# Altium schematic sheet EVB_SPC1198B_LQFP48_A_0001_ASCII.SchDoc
size A4; 项目编号: SPSZ2023-052501A; 项目名称: 三相PFC-2.2KW压机+700W风机
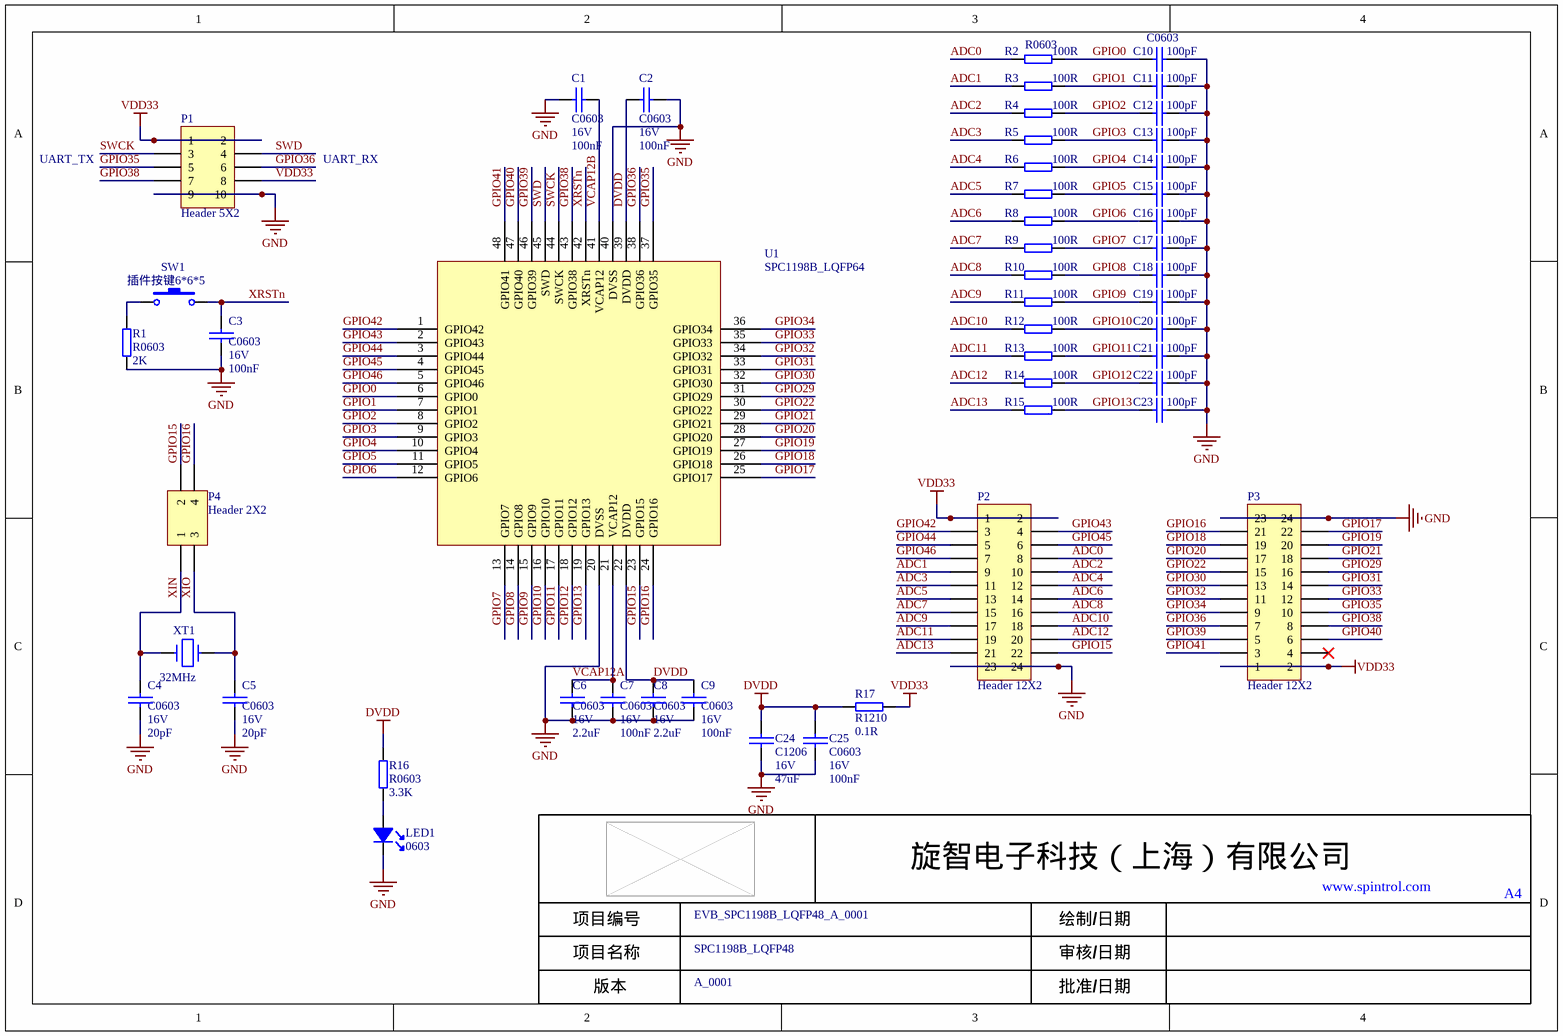
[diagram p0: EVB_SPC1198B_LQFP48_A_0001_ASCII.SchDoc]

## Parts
C1  4.物料简述: C0603  3.物料描述（系统）: 16V  [0603C]  (hidden comment: 100nF)
C2  4.物料简述: C0603  3.物料描述（系统）: 16V  [0603C]  (hidden comment: 100nF)
C3  4.物料简述: C0603  3.物料描述（系统）: 16V  [0603C]  (hidden comment: 100nF)
C4  4.物料简述: C0603  3.物料描述（系统）: 16V  [0603C]  (hidden comment: 20pF)
C5  4.物料简述: C0603  3.物料描述（系统）: 16V  [0603C]  (hidden comment: 20pF)
C6  4.物料简述: C0603  3.物料描述（系统）: 16V  [0603C]  (hidden comment: 2.2uF)
C7  4.物料简述: C0603  3.物料描述（系统）: 16V  [0603C]  (hidden comment: 100nF)
C8  4.物料简述: C0603  3.物料描述（系统）: 16V  [0603C]  (hidden comment: 2.2uF)
C9  4.物料简述: C0603  3.物料描述（系统）: 16V  [0603C]  (hidden comment: 100nF)
C10  4.物料简述: C0603  [0603C]  (hidden comment: 100pF)
C11  100pF  [0603C]
C12  100pF  [0603C]
C13  100pF  [0603C]
C14  100pF  [0603C]
C15  100pF  [0603C]
C16  100pF  [0603C]
C17  100pF  [0603C]
C18  100pF  [0603C]
C19  100pF  [0603C]
C20  100pF  [0603C]
C21  100pF  [0603C]
C22  100pF  [0603C]
C23  100pF  [0603C]
C24  4.物料简述: C1206  3.物料描述（系统）: 16V  [1206C]  (hidden comment: 47uF)
C25  4.物料简述: C0603  3.物料描述（系统）: 16V  [0603C]  (hidden comment: 100nF)
LED1  4.物料简述: 0603  [LED0603]
P1  Header 5X2  [HDR2X5]
P2  Header 12X2  [HDR2X12]
P3  Header 12X2  [HDR2X12]
P4  Header 2X2  [HDR2X2]
R1  4.物料简述: R0603  [0603R]  (hidden comment: 2K)
R2  4.物料简述: R0603  [0603R]  (hidden comment: 100R)
R3  100R  [0603R]
R4  100R  [0603R]
R5  100R  [0603R]
R6  100R  [0603R]
R7  100R  [0603R]
R8  100R  [0603R]
R9  100R  [0603R]
R10  100R  [0603R]
R11  100R  [0603R]
R12  100R  [0603R]
R13  100R  [0603R]
R14  100R  [0603R]
R15  100R  [0603R]
R16  4.物料简述: R0603  [0603R]  (hidden comment: 3.3K)
R17  4.物料简述: R1210  [1210R]  (hidden comment: 0.1R)
SW1  插件按键6*6*5  [Key_6*6]
U1  SPC1198B_LQFP64  [LQFP-48-0.5]
XT1  32MHz  [XT-HI]

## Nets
DVDD: C2.2 C8.2 C9.2 C24.2 C25.2 R16.1 R17.1 U1.22(DVDD) U1.39(DVDD)
GND: C1.2 C2.1 C3.1 C4.1 C5.1 C6.1 C7.1 C8.1 C9.1 C10.2 C11.2 C12.2 C13.2 C14.2 C15.2 C16.2 C17.2 C18.2 C19.2 C20.2 C21.2 C22.2 C23.2 C24.1 C25.1 LED1.K P1.9 P1.10 P2.23 P2.24 P3.23 P3.24 R1.2 U1.20(DVSS) U1.40(DVSS)
VDD33: P1.1 P1.2 P1.8 P2.1 P2.2 P3.1 P3.2 R17.2
ADC0: P2.8 R2.2
ADC1: P2.9 R3.2
ADC2: P2.10 R4.2
ADC3: P2.11 R5.2
ADC4: P2.12 R6.2
ADC5: P2.13 R7.2
ADC6: P2.14 R8.2
ADC7: P2.15 R9.2
ADC8: P2.16 R10.2
ADC9: P2.17 R11.2
ADC10: P2.18 R12.2
ADC11: P2.19 R13.2
ADC12: P2.20 R14.2
ADC13: P2.21 R15.2
GPIO0: C10.1 R2.1 U1.6(GPIO0)
GPIO1: C11.1 R3.1 U1.7(GPIO1)
GPIO2: C12.1 R4.1 U1.8(GPIO2)
GPIO3: C13.1 R5.1 U1.9(GPIO3)
GPIO4: C14.1 R6.1 U1.10(GPIO4)
GPIO5: C15.1 R7.1 U1.11(GPIO5)
GPIO6: C16.1 R8.1 U1.12(GPIO6)
GPIO7: C17.1 R9.1 U1.13(GPIO7)
GPIO8: C18.1 R10.1 U1.14(GPIO8)
GPIO9: C19.1 R11.1 U1.15(GPIO9)
GPIO10: C20.1 R12.1 U1.16(GPIO10)
GPIO11: C21.1 R13.1 U1.17(GPIO11)
GPIO12: C22.1 R14.1 U1.18(GPIO12)
GPIO13: C23.1 R15.1 U1.19(GPIO13)
GPIO15: P2.22 P4.2 U1.23(GPIO15)
GPIO16: P3.21 P4.4 U1.24(GPIO16)
GPIO17: P3.22 U1.25(GPIO17)
GPIO18: P3.19 U1.26(GPIO18)
GPIO19: P3.20 U1.27(GPIO19)
GPIO20: P3.17 U1.28(GPIO20)
GPIO21: P3.18 U1.29(GPIO21)
GPIO22: P3.15 U1.30(GPIO22)
GPIO29: P3.16 U1.31(GPIO29)
GPIO30: P3.13 U1.32(GPIO30)
GPIO31: P3.14 U1.33(GPIO31)
GPIO32: P3.11 U1.34(GPIO32)
GPIO33: P3.12 U1.35(GPIO33)
GPIO34: P3.9 U1.36(GPIO34)
GPIO35: P1.5 P3.10 U1.37(GPIO35)
GPIO36: P1.6 P3.7 U1.38(GPIO36)
GPIO38: P1.7 P3.8 U1.43(GPIO38)
GPIO39: P3.5 U1.46(GPIO39)
GPIO40: P3.6 U1.47(GPIO40)
GPIO41: P3.3 U1.48(GPIO41)
GPIO42: P2.3 U1.1(GPIO42)
GPIO43: P2.4 U1.2(GPIO43)
GPIO44: P2.5 U1.3(GPIO44)
GPIO45: P2.6 U1.4(GPIO45)
GPIO46: P2.7 U1.5(GPIO46)
SWCK: P1.3 U1.44(SWCK)
SWD: P1.4 U1.45(SWD)
VCAP12A: C6.2 C7.2 U1.21(VCAP12)
VCAP12B: C1.1 U1.41(VCAP12)
XIN: C4.2 P4.1 XT1.1
XIO: C5.2 P4.3 XT1.2
XRSTn: C3.2 SW1.1 U1.42(XRSTn)
NetLED1_A: LED1.A R16.2
NetR1_1: R1.1 SW1.2

Not connected (* = marked no-connect by the designer): P3 4*

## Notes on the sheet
- UART_TX
- UART_RX
- EVB_SPC1198B_LQFP48_A_0001
- SPC1198B_LQFP48
- A_0001

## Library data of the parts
C1-C25 = Capacitor: 无极性电容
LED1 = LED: 发光二极管
P1 = Header 5X2: Header, 5-Pin, Dual row
P2 P3 = Header 12X2: Header, 12-Pin, Dual row
P4 = Header 2X2: Header, 2-Pin, Dual row
R1-R17 = Resistance: 电阻
SW1 = SW-PB: Switch
XT1 = CRYSTAL-2P: 4.物料简述: C295082; 3.物料描述（系统）: XIHCELNANF-32MHZ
